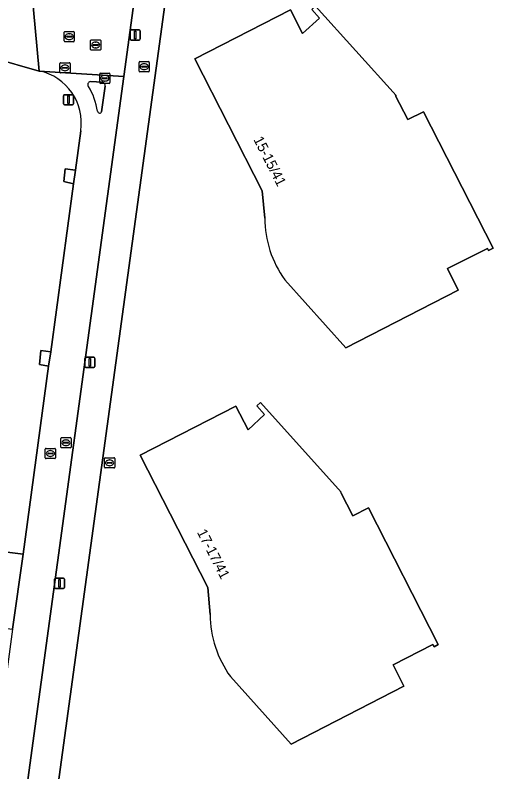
# Model space of a CAD drawing. Extents: x 161402 to 161933, y 381647 to 382315.
# Drawn here: x 161759 to 161806.7, y 382001.8 to 382075.9 of the extents above; entities that cross this region are included whole.
import ezdxf

# ---------------------------------------------------------------- set-up
doc = ezdxf.new("R2010")
doc.units = 0
for name, color, linetype in [('IMGEO_Brandkraan', 7, 'Continuous'), ('IMGEO_Erf', 7, 'Continuous'), ('IMGEO_Groenvoorziening', 7, 'Continuous'), ('IMGEO_Lichtmast', 7, 'Continuous'), ('IMGEO_Pand', 7, 'Continuous'), ('IMGEO_Pand_nummerreeks', 7, 'Continuous'), ('IMGEO_Rijbaan_lokaal_gesloten', 7, 'Continuous'), ('IMGEO_Rijbaan_lokaal_open', 7, 'Continuous'), ('IMGEO_Rioolput', 7, 'Continuous'), ('IMGEO_Verkeersbordpaal', 7, 'Continuous'), ('IMGEO_Verkeerseiland_gesloten', 7, 'Continuous'), ('IMGEO_Voetpad_open', 7, 'Continuous')]:
    doc.layers.add(name, color=color, linetype=linetype)

msp = doc.modelspace()

# ---------------------------------------------------------------- linework, layer by layer
at = {"layer": 'IMGEO_Brandkraan'}
for p, q in [((161771.177, 382070.428), (161771.177, 382071.28)), ((161771.252, 382071.354), (161772.104, 382071.354)), ((161771.479, 382070.897), (161771.877, 382070.897)), ((161771.665, 382071.134), (161771.69, 382071.134)), ((161772.178, 382071.28), (161772.178, 382070.428)), ((161772.104, 382070.354), (161771.252, 382070.354)), ((161771.436, 382070.848), (161771.436, 382070.86)), ((161771.874, 382070.811), (161771.476, 382070.811)), ((161771.688, 382070.574), (161771.663, 382070.574)), ((161771.92, 382070.86), (161771.92, 382070.848))]:
    msp.add_line(p, q, dxfattribs=at)
for points in [[(161771.177, 382070.428), (161771.177, 382071.28)], [(161771.252, 382071.354), (161772.104, 382071.354)], [(161772.178, 382071.28), (161772.178, 382070.428)], [(161772.104, 382070.354), (161771.252, 382070.354)]]:
    msp.add_lwpolyline(points, dxfattribs=at)
for centre, radius, start, end in [((161771.254, 382071.278), 0.0765, 91.55205, 178.44795), ((161771.254, 382071.278), 0.0765, 91.55205, 178.44795), ((161771.476, 382070.857), 0.0403, 85.87752, 175.75265), ((161771.881, 382070.859), 0.0386, 1.73085, 96.63898), ((161772.102, 382071.278), 0.0765, 1.55205, 88.44795), ((161772.102, 382071.278), 0.0765, 1.55205, 88.44795), ((161771.254, 382070.43), 0.0765, 181.55205, 268.44795), ((161771.254, 382070.43), 0.0765, 181.55205, 268.44795), ((161771.473, 382070.847), 0.0366, 178.93798, 274.71019), ((161771.877, 382070.854), 0.043, 264.86636, 352.45326), ((161772.102, 382070.43), 0.0765, 271.55205, 358.44795), ((161772.102, 382070.43), 0.0765, 271.55205, 358.44795)]:
    msp.add_arc(centre, radius, start, end, dxfattribs=at)
for centre, major_axis, ratio, start_param, end_param in [((161771.664, 382070.854), (-0.387, 0.002), 0.722429, 4.712389, 7.853982), ((161771.689, 382070.854), (-0.39, 0.002), 0.717154, 1.570796, 4.712389)]:
    msp.add_ellipse(centre, major_axis=major_axis, ratio=ratio, start_param=start_param, end_param=end_param, dxfattribs=at)
at = {"layer": 'IMGEO_Erf'}
for points in [[(161773.703, 382076.916), (161762.821, 381997.456), (161761.87, 381990.395), (161771.057, 381972.467), (161771.173, 381972.261), (161771.575, 381971.547), (161771.72, 381971.27), (161774.483, 381972.736)], [(161783.505, 382056.018), (161783.263, 382058.701), (161776.645, 382071.618), (161786.037, 382076.43), (161787.222, 382074.116), (161788.878, 382075.604), (161788.117, 382076.444), (161788.484, 382076.777), (161796.387, 382068.043), (161796.339, 382068), (161797.532, 382065.679), (161799.064, 382066.435), (161805.902, 382053.086)], [(161805.902, 382053.086), (161805.443, 382052.848), (161805.338, 382053.051), (161801.419, 382051.074), (161802.476, 382048.979), (161791.458, 382043.303), (161785.474, 382049.988)], [(161778.143, 382017.19), (161777.917, 382019.851), (161771.287, 382032.794), (161780.678, 382037.609), (161781.865, 382035.293), (161783.487, 382036.775), (161782.716, 382037.629), (161783.087, 382037.964), (161791.008, 382029.192), (161790.963, 382029.151), (161792.159, 382026.86), (161793.688, 382027.645), (161800.527, 382014.251)], [(161800.527, 382014.251), (161800.11, 382014.03), (161799.998, 382014.242), (161796.087, 382012.25), (161797.153, 382010.158), (161786.098, 382004.476), (161780.132, 382011.119)]]:
    msp.add_lwpolyline(points, dxfattribs=at)
for centre, radius, start, end in [((161793.818, 382056.049), 10.313, 180.17191, 215.99533), ((161788.828, 382017.329), 10.686, 180.74706, 215.53293)]:
    msp.add_arc(centre, radius, start, end, dxfattribs=at)
at = {"layer": 'IMGEO_Groenvoorziening'}
for points in [[(161761.399, 382070.432), (161756.821, 382071.728), (161755.957, 382071.985), (161755.857, 382072.012), (161757.406, 382069.298), (161756.706, 382064.555), (161756.164, 382060.542), (161756.757, 382057.995), (161756.012, 382046.374), (161754.267, 382033.516), (161753.288, 382023.926), (161759.804, 382023.11), (161762.302, 382041.53)], [(161762.302, 382041.53), (161761.4, 382041.699), (161761.556, 382043.048), (161762.518, 382042.922), (161764.745, 382059.38), (161763.807, 382059.601), (161763.945, 382060.856), (161764.936, 382060.736), (161765.457, 382064.59)]]:
    msp.add_lwpolyline(points, dxfattribs=at)
msp.add_arc((161760.362, 382065.381), 5.156, 351.17098, 78.39865, dxfattribs=at)
at = {"layer": 'IMGEO_Lichtmast'}
for p, q in [((161770.309, 382073.571), (161770.309, 382074.371)), ((161770.309, 382074.371), (161770.309, 382073.571)), ((161770.409, 382074.471), (161771.199, 382074.471)), ((161771.199, 382074.471), (161770.409, 382074.471)), ((161771.299, 382074.371), (161771.299, 382073.571)), ((161771.299, 382073.571), (161771.299, 382074.371)), ((161771.199, 382073.471), (161770.409, 382073.471)), ((161770.409, 382073.471), (161771.199, 382073.471)), ((161765.861, 382041.487), (161765.861, 382042.287)), ((161765.861, 382042.287), (161765.861, 382041.487)), ((161765.961, 382042.387), (161766.751, 382042.387)), ((161766.751, 382042.387), (161765.961, 382042.387)), ((161766.851, 382042.287), (161766.851, 382041.487)), ((161766.851, 382041.487), (161766.851, 382042.287)), ((161766.751, 382041.387), (161765.961, 382041.387)), ((161765.961, 382041.387), (161766.751, 382041.387)), ((161762.886, 382019.851), (161762.886, 382020.651)), ((161762.886, 382020.651), (161762.886, 382019.851)), ((161762.986, 382020.751), (161763.776, 382020.751)), ((161763.776, 382020.751), (161762.986, 382020.751)), ((161763.876, 382020.651), (161763.876, 382019.851)), ((161763.876, 382019.851), (161763.876, 382020.651)), ((161763.776, 382019.751), (161762.986, 382019.751)), ((161762.986, 382019.751), (161763.776, 382019.751))]:
    msp.add_line(p, q, dxfattribs=at)
for points in [[(161770.729, 382074.346), (161770.879, 382074.346), (161770.879, 382073.596), (161770.729, 382073.596), (161770.729, 382074.346)], [(161766.281, 382042.262), (161766.431, 382042.262), (161766.431, 382041.512), (161766.281, 382041.512), (161766.281, 382042.262)], [(161763.306, 382020.626), (161763.456, 382020.626), (161763.456, 382019.876), (161763.306, 382019.876), (161763.306, 382020.626)]]:
    msp.add_lwpolyline(points, dxfattribs=at)
for centre, start, end in [((161770.409, 382074.371), 90, 180), ((161770.409, 382074.371), 90, 180), ((161771.199, 382074.371), 0, 90), ((161771.199, 382074.371), 360, 90), ((161770.409, 382073.571), 180, 270), ((161770.409, 382073.571), 180, 270), ((161771.199, 382073.571), 270, 0), ((161771.199, 382073.571), 270, 0), ((161765.961, 382042.287), 90, 180), ((161765.961, 382042.287), 90, 180), ((161766.751, 382042.287), 0, 90), ((161766.751, 382042.287), 360, 90), ((161765.961, 382041.487), 180, 270), ((161765.961, 382041.487), 180, 270), ((161766.751, 382041.487), 270, 0), ((161766.751, 382041.487), 270, 0), ((161762.986, 382020.651), 90, 180), ((161762.986, 382020.651), 90, 180), ((161763.776, 382020.651), 0, 90), ((161763.776, 382020.651), 360, 90), ((161762.986, 382019.851), 180, 270), ((161762.986, 382019.851), 180, 270), ((161763.776, 382019.851), 270, 0), ((161763.776, 382019.851), 270, 0)]:
    msp.add_arc(centre, 0.1, start, end, dxfattribs=at)
at = {"layer": 'IMGEO_Pand'}
for points in [[(161796.339, 382068), (161796.387, 382068.043), (161788.484, 382076.777), (161788.117, 382076.444), (161788.878, 382075.604), (161787.222, 382074.116), (161786.037, 382076.43), (161776.645, 382071.618), (161783.263, 382058.701), (161783.505, 382056.018)], [(161785.474, 382049.988), (161791.458, 382043.303), (161802.476, 382048.979), (161801.419, 382051.074), (161805.338, 382053.051), (161805.443, 382052.848), (161805.902, 382053.086), (161799.064, 382066.435), (161797.532, 382065.679), (161796.339, 382068)], [(161793.688, 382027.645), (161792.159, 382026.86), (161790.963, 382029.151), (161791.008, 382029.192), (161783.087, 382037.964), (161782.716, 382037.629), (161783.487, 382036.775), (161781.865, 382035.293), (161780.678, 382037.609), (161771.287, 382032.794), (161777.917, 382019.851), (161778.143, 382017.19)], [(161780.132, 382011.119), (161786.098, 382004.476), (161797.153, 382010.158), (161796.087, 382012.25), (161799.998, 382014.242), (161800.11, 382014.03), (161800.527, 382014.251), (161793.688, 382027.645)]]:
    msp.add_lwpolyline(points, dxfattribs=at)
for centre, radius, start, end in [((161793.818, 382056.049), 10.313, 180.17191, 215.99533), ((161788.828, 382017.329), 10.686, 180.74706, 215.53293)]:
    msp.add_arc(centre, radius, start, end, dxfattribs=at)
at = {"layer": 'IMGEO_Rijbaan_lokaal_gesloten'}
for points in [[(161760.641, 382078.597), (161761.399, 382070.432), (161769.695, 382069.904), (161770.706, 382077.294), (161772.36, 382089.55), (161773.576, 382098.504), (161773.605, 382098.746)], [(161723.499, 382081.074), (161725.039, 382080.585), (161727.317, 382079.877), (161729.208, 382079.301), (161731.057, 382078.758), (161732.976, 382078.22), (161743.495, 382075.362), (161755.857, 382072.012), (161755.957, 382071.985), (161756.821, 382071.728), (161761.399, 382070.432), (161760.641, 382078.597)]]:
    msp.add_lwpolyline(points, dxfattribs=at)
at = {"layer": 'IMGEO_Rijbaan_lokaal_open'}
for points in [[(161759.283, 381993.653), (161759.49, 381995.39), (161759.969, 381998.846), (161769.695, 382069.904), (161761.399, 382070.432)], [(161766.405, 382069.401), (161767.589, 382069.34)], [(161767.85, 382068.955), (161767.503, 382066.437)], [(161765.457, 382064.59), (161764.936, 382060.736), (161764.745, 382059.38), (161762.518, 382042.922), (161762.302, 382041.53), (161759.804, 382023.11), (161758.766, 382015.767), (161757.438, 382005.955), (161756.786, 382001.123), (161756.622, 381999.921), (161756.039, 381995.697)]]:
    msp.add_lwpolyline(points, dxfattribs=at)
for centre, radius, start, end in [((161760.362, 382065.381), 5.156, 351.17098, 78.39865), ((161766.445, 382069.108), 0.295, 97.80765, 217.59057), ((161760.753, 382065.527), 6.431, 8.58836, 31.93096), ((161767.51, 382069.005), 0.344, 351.60665, 76.66178), ((161767.313, 382066.506), 0.202, 185.32401, 340.10144)]:
    msp.add_arc(centre, radius, start, end, dxfattribs=at)
at = {"layer": 'IMGEO_Rioolput'}
for p, q in [((161763.83, 382073.376), (161763.83, 382074.228)), ((161763.905, 382074.302), (161764.757, 382074.302)), ((161764.318, 382074.082), (161764.343, 382074.082)), ((161764.831, 382074.228), (161764.831, 382073.376)), ((161764.757, 382073.302), (161763.905, 382073.302)), ((161764.089, 382073.796), (161764.089, 382073.808)), ((161764.527, 382073.759), (161764.129, 382073.759)), ((161764.132, 382073.845), (161764.53, 382073.845)), ((161764.341, 382073.522), (161764.316, 382073.522)), ((161764.573, 382073.808), (161764.573, 382073.796)), ((161766.424, 382072.557), (161766.424, 382073.409)), ((161766.499, 382073.483), (161767.351, 382073.483)), ((161766.912, 382073.263), (161766.937, 382073.263)), ((161767.425, 382073.409), (161767.425, 382072.557)), ((161767.351, 382072.483), (161766.499, 382072.483)), ((161766.683, 382072.977), (161766.683, 382072.989)), ((161767.121, 382072.94), (161766.723, 382072.94)), ((161766.726, 382073.026), (161767.124, 382073.026)), ((161766.935, 382072.703), (161766.91, 382072.703)), ((161767.167, 382072.989), (161767.167, 382072.977)), ((161763.408, 382070.319), (161763.408, 382071.171)), ((161763.483, 382071.245), (161764.335, 382071.245)), ((161763.896, 382071.025), (161763.921, 382071.025)), ((161764.409, 382071.171), (161764.409, 382070.319)), ((161764.335, 382070.245), (161763.483, 382070.245)), ((161763.667, 382070.739), (161763.667, 382070.751)), ((161764.105, 382070.702), (161763.707, 382070.702)), ((161763.71, 382070.788), (161764.108, 382070.788)), ((161763.919, 382070.465), (161763.894, 382070.465)), ((161764.151, 382070.751), (161764.151, 382070.739)), ((161767.321, 382069.301), (161767.321, 382070.153)), ((161767.396, 382070.227), (161768.248, 382070.227)), ((161768.322, 382070.153), (161768.322, 382069.301)), ((161767.58, 382069.721), (161767.58, 382069.733)), ((161768.018, 382069.684), (161767.62, 382069.684)), ((161767.623, 382069.77), (161768.021, 382069.77)), ((161767.832, 382069.447), (161767.807, 382069.447)), ((161767.809, 382070.007), (161767.834, 382070.007)), ((161768.064, 382069.733), (161768.064, 382069.721)), ((161768.248, 382069.227), (161767.396, 382069.227)), ((161763.511, 382033.591), (161763.511, 382034.443)), ((161763.586, 382034.517), (161764.438, 382034.517)), ((161763.77, 382034.011), (161763.77, 382034.023)), ((161764.208, 382033.974), (161763.81, 382033.974)), ((161763.813, 382034.06), (161764.211, 382034.06)), ((161763.999, 382034.297), (161764.024, 382034.297)), ((161764.254, 382034.023), (161764.254, 382034.011)), ((161764.512, 382034.443), (161764.512, 382033.591)), ((161761.983, 382032.54), (161761.983, 382033.392)), ((161762.058, 382033.466), (161762.91, 382033.466)), ((161762.471, 382033.246), (161762.496, 382033.246)), ((161762.984, 382033.392), (161762.984, 382032.54)), ((161764.438, 382033.517), (161763.586, 382033.517)), ((161764.022, 382033.737), (161763.997, 382033.737)), ((161762.91, 382032.466), (161762.058, 382032.466)), ((161762.242, 382032.96), (161762.242, 382032.972)), ((161762.68, 382032.923), (161762.282, 382032.923)), ((161762.285, 382033.009), (161762.683, 382033.009)), ((161762.494, 382032.686), (161762.469, 382032.686)), ((161762.726, 382032.972), (161762.726, 382032.96)), ((161767.788, 382031.625), (161767.788, 382032.477)), ((161767.863, 382032.551), (161768.715, 382032.551)), ((161768.789, 382032.477), (161768.789, 382031.625)), ((161768.047, 382032.045), (161768.047, 382032.057)), ((161768.485, 382032.008), (161768.087, 382032.008)), ((161768.09, 382032.094), (161768.488, 382032.094)), ((161768.299, 382031.771), (161768.274, 382031.771)), ((161768.276, 382032.331), (161768.301, 382032.331)), ((161768.531, 382032.057), (161768.531, 382032.045)), ((161768.715, 382031.551), (161767.863, 382031.551))]:
    msp.add_line(p, q, dxfattribs=at)
for points in [[(161763.83, 382073.376), (161763.83, 382074.228)], [(161763.905, 382074.302), (161764.757, 382074.302)], [(161764.831, 382074.228), (161764.831, 382073.376)], [(161764.757, 382073.302), (161763.905, 382073.302)], [(161766.424, 382072.557), (161766.424, 382073.409)], [(161766.499, 382073.483), (161767.351, 382073.483)], [(161767.425, 382073.409), (161767.425, 382072.557)], [(161767.351, 382072.483), (161766.499, 382072.483)], [(161763.408, 382070.319), (161763.408, 382071.171)], [(161763.483, 382071.245), (161764.335, 382071.245)], [(161764.409, 382071.171), (161764.409, 382070.319)], [(161764.335, 382070.245), (161763.483, 382070.245)], [(161767.321, 382069.301), (161767.321, 382070.153)], [(161767.396, 382070.227), (161768.248, 382070.227)], [(161768.322, 382070.153), (161768.322, 382069.301)], [(161768.248, 382069.227), (161767.396, 382069.227)], [(161763.511, 382033.591), (161763.511, 382034.443)], [(161763.586, 382034.517), (161764.438, 382034.517)], [(161764.512, 382034.443), (161764.512, 382033.591)], [(161761.983, 382032.54), (161761.983, 382033.392)], [(161762.058, 382033.466), (161762.91, 382033.466)], [(161762.984, 382033.392), (161762.984, 382032.54)], [(161764.438, 382033.517), (161763.586, 382033.517)], [(161762.91, 382032.466), (161762.058, 382032.466)], [(161767.788, 382031.625), (161767.788, 382032.477)], [(161767.863, 382032.551), (161768.715, 382032.551)], [(161768.789, 382032.477), (161768.789, 382031.625)], [(161768.715, 382031.551), (161767.863, 382031.551)]]:
    msp.add_lwpolyline(points, dxfattribs=at)
for centre, radius, start, end in [((161763.907, 382074.226), 0.0765, 91.55205, 178.44795), ((161763.907, 382074.226), 0.0765, 91.55205, 178.44795), ((161764.755, 382074.226), 0.0765, 1.55205, 88.44795), ((161764.755, 382074.226), 0.0765, 1.55205, 88.44795), ((161763.907, 382073.378), 0.0765, 181.55205, 268.44795), ((161763.907, 382073.378), 0.0765, 181.55205, 268.44795), ((161764.129, 382073.805), 0.0403, 85.87752, 175.75265), ((161764.126, 382073.795), 0.0366, 178.93798, 274.71019), ((161764.53, 382073.802), 0.043, 264.86636, 352.45326), ((161764.534, 382073.807), 0.0386, 1.73085, 96.63898), ((161764.755, 382073.378), 0.0765, 271.55205, 358.44795), ((161764.755, 382073.378), 0.0765, 271.55205, 358.44795), ((161766.501, 382073.407), 0.0765, 91.55205, 178.44795), ((161766.501, 382073.407), 0.0765, 91.55205, 178.44795), ((161767.349, 382073.407), 0.0765, 1.55205, 88.44795), ((161767.349, 382073.407), 0.0765, 1.55205, 88.44795), ((161766.501, 382072.559), 0.0765, 181.55205, 268.44795), ((161766.501, 382072.559), 0.0765, 181.55205, 268.44795), ((161766.723, 382072.986), 0.0403, 85.87752, 175.75265), ((161766.72, 382072.976), 0.0366, 178.93798, 274.71019), ((161767.124, 382072.983), 0.043, 264.86636, 352.45326), ((161767.128, 382072.988), 0.0386, 1.73085, 96.63898), ((161767.349, 382072.559), 0.0765, 271.55205, 358.44795), ((161767.349, 382072.559), 0.0765, 271.55205, 358.44795), ((161763.485, 382071.169), 0.0765, 91.55205, 178.44795), ((161763.485, 382071.169), 0.0765, 91.55205, 178.44795), ((161764.333, 382071.169), 0.0765, 1.55205, 88.44795), ((161764.333, 382071.169), 0.0765, 1.55205, 88.44795), ((161763.485, 382070.321), 0.0765, 181.55205, 268.44795), ((161763.485, 382070.321), 0.0765, 181.55205, 268.44795), ((161763.707, 382070.748), 0.0403, 85.87752, 175.75265), ((161763.704, 382070.738), 0.0366, 178.93798, 274.71019), ((161764.108, 382070.745), 0.043, 264.86636, 352.45326), ((161764.112, 382070.75), 0.0386, 1.73085, 96.63898), ((161764.333, 382070.321), 0.0765, 271.55205, 358.44795), ((161764.333, 382070.321), 0.0765, 271.55205, 358.44795), ((161767.398, 382070.151), 0.0765, 91.55205, 178.44795), ((161767.398, 382070.151), 0.0765, 91.55205, 178.44795), ((161768.246, 382070.151), 0.0765, 1.55205, 88.44795), ((161768.246, 382070.151), 0.0765, 1.55205, 88.44795), ((161767.62, 382069.73), 0.0403, 85.87752, 175.75265), ((161767.617, 382069.72), 0.0366, 178.93798, 274.71019), ((161768.021, 382069.727), 0.043, 264.86636, 352.45326), ((161768.025, 382069.732), 0.0386, 1.73085, 96.63898), ((161767.398, 382069.303), 0.0765, 181.55205, 268.44795), ((161767.398, 382069.303), 0.0765, 181.55205, 268.44795), ((161768.246, 382069.303), 0.0765, 271.55205, 358.44795), ((161768.246, 382069.303), 0.0765, 271.55205, 358.44795), ((161763.588, 382034.441), 0.0765, 91.55205, 178.44795), ((161763.588, 382034.441), 0.0765, 91.55205, 178.44795), ((161763.81, 382034.02), 0.0403, 85.87752, 175.75265), ((161763.807, 382034.01), 0.0366, 178.93798, 274.71019), ((161764.211, 382034.017), 0.043, 264.86636, 352.45326), ((161764.215, 382034.022), 0.0386, 1.73085, 96.63898), ((161764.436, 382034.441), 0.0765, 1.55205, 88.44795), ((161764.436, 382034.441), 0.0765, 1.55205, 88.44795), ((161762.06, 382033.39), 0.0765, 91.55205, 178.44795), ((161762.06, 382033.39), 0.0765, 91.55205, 178.44795), ((161762.908, 382033.39), 0.0765, 1.55205, 88.44795), ((161762.908, 382033.39), 0.0765, 1.55205, 88.44795), ((161763.588, 382033.593), 0.0765, 181.55205, 268.44795), ((161763.588, 382033.593), 0.0765, 181.55205, 268.44795), ((161764.436, 382033.593), 0.0765, 271.55205, 358.44795), ((161764.436, 382033.593), 0.0765, 271.55205, 358.44795), ((161762.06, 382032.542), 0.0765, 181.55205, 268.44795), ((161762.06, 382032.542), 0.0765, 181.55205, 268.44795), ((161762.282, 382032.969), 0.0403, 85.87752, 175.75265), ((161762.279, 382032.959), 0.0366, 178.93798, 274.71019), ((161762.683, 382032.966), 0.043, 264.86636, 352.45326), ((161762.687, 382032.971), 0.0386, 1.73085, 96.63898), ((161762.908, 382032.542), 0.0765, 271.55205, 358.44795), ((161762.908, 382032.542), 0.0765, 271.55205, 358.44795), ((161767.865, 382032.475), 0.0765, 91.55205, 178.44795), ((161767.865, 382032.475), 0.0765, 91.55205, 178.44795), ((161768.713, 382032.475), 0.0765, 1.55205, 88.44795), ((161768.713, 382032.475), 0.0765, 1.55205, 88.44795), ((161767.865, 382031.627), 0.0765, 181.55205, 268.44795), ((161767.865, 382031.627), 0.0765, 181.55205, 268.44795), ((161768.087, 382032.054), 0.0403, 85.87752, 175.75265), ((161768.084, 382032.044), 0.0366, 178.93798, 274.71019), ((161768.488, 382032.051), 0.043, 264.86636, 352.45326), ((161768.492, 382032.056), 0.0386, 1.73085, 96.63898), ((161768.713, 382031.627), 0.0765, 271.55205, 358.44795), ((161768.713, 382031.627), 0.0765, 271.55205, 358.44795)]:
    msp.add_arc(centre, radius, start, end, dxfattribs=at)
for centre, major_axis, ratio, start_param, end_param in [((161764.317, 382073.802), (-0.387, 0.002), 0.722429, 4.712389, 7.853982), ((161764.342, 382073.802), (-0.39, 0.002), 0.717154, 1.570796, 4.712389), ((161766.911, 382072.983), (-0.387, 0.002), 0.722429, 4.712389, 7.853982), ((161766.936, 382072.983), (-0.39, 0.002), 0.717154, 1.570796, 4.712389), ((161763.895, 382070.745), (-0.387, 0.002), 0.722429, 4.712389, 7.853982), ((161763.92, 382070.745), (-0.39, 0.002), 0.717154, 1.570796, 4.712389), ((161767.808, 382069.727), (-0.387, 0.002), 0.722429, 4.712389, 7.853982), ((161767.833, 382069.727), (-0.39, 0.002), 0.717154, 1.570796, 4.712389), ((161763.998, 382034.017), (-0.387, 0.002), 0.722429, 4.712389, 7.853982), ((161764.023, 382034.017), (-0.39, 0.002), 0.717154, 1.570796, 4.712389), ((161762.47, 382032.966), (-0.387, 0.002), 0.722429, 4.712389, 7.853982), ((161762.495, 382032.966), (-0.39, 0.002), 0.717154, 1.570796, 4.712389), ((161768.275, 382032.051), (-0.387, 0.002), 0.722429, 4.712389, 7.853982), ((161768.3, 382032.051), (-0.39, 0.002), 0.717154, 1.570796, 4.712389)]:
    msp.add_ellipse(centre, major_axis=major_axis, ratio=ratio, start_param=start_param, end_param=end_param, dxfattribs=at)
at = {"layer": 'IMGEO_Verkeersbordpaal'}
for p, q in [((161763.768, 382067.214), (161763.768, 382068.014)), ((161763.768, 382068.014), (161763.768, 382067.214)), ((161763.868, 382068.114), (161764.658, 382068.114)), ((161764.658, 382068.114), (161763.868, 382068.114)), ((161764.758, 382068.014), (161764.758, 382067.214)), ((161764.758, 382067.214), (161764.758, 382068.014)), ((161764.658, 382067.114), (161763.868, 382067.114)), ((161763.868, 382067.114), (161764.658, 382067.114))]:
    msp.add_line(p, q, dxfattribs=at)
msp.add_lwpolyline([(161764.188, 382067.989), (161764.338, 382067.989), (161764.338, 382067.239), (161764.188, 382067.239), (161764.188, 382067.989)], dxfattribs=at)
for centre, start, end in [((161763.868, 382068.014), 90, 180), ((161763.868, 382068.014), 90, 180), ((161764.658, 382068.014), 0, 90), ((161764.658, 382068.014), 360, 90), ((161763.868, 382067.214), 180, 270), ((161763.868, 382067.214), 180, 270), ((161764.658, 382067.214), 270, 0), ((161764.658, 382067.214), 270, 0)]:
    msp.add_arc(centre, 0.1, start, end, dxfattribs=at)
at = {"layer": 'IMGEO_Verkeerseiland_gesloten'}
for points in [[(161767.589, 382069.34), (161766.405, 382069.401)], [(161767.503, 382066.437), (161767.85, 382068.955)]]:
    msp.add_lwpolyline(points, dxfattribs=at)
for centre, radius, start, end in [((161766.445, 382069.108), 0.295, 97.80765, 217.59057), ((161760.753, 382065.527), 6.431, 8.58836, 31.93096), ((161767.51, 382069.005), 0.344, 351.60665, 76.66178), ((161767.313, 382066.506), 0.202, 185.32401, 340.10144)]:
    msp.add_arc(centre, radius, start, end, dxfattribs=at)
at = {"layer": 'IMGEO_Voetpad_open'}
for points in [[(161761.87, 381990.395), (161762.821, 381997.456), (161773.703, 382076.916), (161776.756, 382099.569), (161777.238, 382100.058), (161781.67, 382104.382), (161804.249, 382126.529), (161826.48, 382148.395), (161845.138, 382166.658), (161857.746, 382179.014)], [(161773.605, 382098.746), (161773.576, 382098.504), (161774.632, 382098.337), (161773.418, 382089.408), (161772.36, 382089.55), (161770.706, 382077.294), (161769.695, 382069.904), (161759.969, 381998.846), (161759.49, 381995.39), (161759.283, 381993.653)]]:
    msp.add_lwpolyline(points, dxfattribs=at)
for points in [[(161764.936, 382060.736), (161763.945, 382060.856), (161763.807, 382059.601), (161764.745, 382059.38)], [(161762.518, 382042.922), (161761.556, 382043.048), (161761.4, 382041.699), (161762.302, 382041.53)], [(161759.804, 382023.11), (161753.288, 382023.926), (161752.877, 382021.496), (161749.539, 382020.701), (161753.788, 382016.422), (161758.766, 382015.767)]]:
    msp.add_lwpolyline(points, close=True, dxfattribs=at)

# ---------------------------------------------------------------- texts
at = {"layer": 'IMGEO_Pand_nummerreeks'}
for s, rotation, p in [('15-15/41', 297.12934, (161782.37, 382063.734)), ('17-17/41', 297.12361, (161776.832, 382025.258))]:
    msp.add_text(s, height=1, rotation=rotation, dxfattribs=at).set_placement(p)

doc.saveas('drawing.dxf')
